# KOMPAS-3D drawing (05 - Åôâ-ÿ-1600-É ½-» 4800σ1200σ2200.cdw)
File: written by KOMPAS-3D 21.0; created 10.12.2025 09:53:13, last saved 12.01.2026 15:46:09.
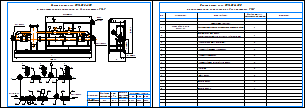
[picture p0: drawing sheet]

Sheets 1-2: A3, landscape

Document properties: Автор: RaskoAdmin; Форматы листов документа: 2xA3; Полное имя файла: \\ur38nt01\Departments\КТО\КБ ПУРДГ\Заявки\Прайс-лист на типовые шкафы ГРПШ\ПУГ-Ш-1600-Р л-п 4800х1200х2200.cdw

Title block, sheet 1: sheet number: 1; Количество листов документа: 2; Форматы листов документа: A3; stored path: \\ur38nt01\Departments\КТО\КБ ПУРДГ\Заявки\Прайс-лист на типовые шкафы ГРПШ\ПУГ-ШУЭО-65-Р л-п.cdw
Title block, sheet 2: sheet number: 2

Views: Вид 1
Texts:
  ЀdȀ
  Пункт учета газа ПУГ-Ш Ду200
  с измерительным комплексом на базе счетчика РГ-Р
  Вход Ду200
  Выход Ду200
  Н max
  Условный
  проход Ду, мм
  Qmax,
  Диапазон
  измерений
  Qmin/Qmax
  Габаритные размеры
  А, мм
  В, мм
  Н, мм
  ПУГ-Ш-1600-Р
  Поз.
  Условный проход
  расходомера Ду 200, мм
  СГ-ЭК-Р-(0,2...2,0)-
  Стандартные изделия
  Измерительный комплекс с ротационным счетчиком Ду200
  Фильтр газа ФГ Ду200
  (Оснащен индикатором перепада давления ДПД)
  Кран кнопочный под манометр
  Кран шаровой штуцерный Ду20
  Кран шаровый Ду150
  Кран шаровый с мехприводом Ду200
  Манометр
  Отвод Ду150
  Фланец Ду150
  Фланец Ду200
  Ду20
  Свеча
  POLYLINE_STYLE_0.18_RGB_0_0_0
  POLYLINE_STYLE_0.77_RGB_0_0_0
  PHANTOM_RGB_255_0_191_SC_1_THICK_0.15
  СONTINUOUS_RGB_0_0_0_THICK_0.25
  K5LT32768_RGB_0_0_0_THICK_0.25
  K5LT32769_RGB_128_128_128_THICK_0.25
  K5LT32770_RGB_0_0_0_THICK_0.7
  ACISOTGL_RGB_255_0_0_SC_1_THICK_0.2
  POLYLINE_STYLE_0.50_RGB_0_0_0
  ACISOTGL_RGB_0_0_0_SC_1_THICK_0.18
  ACISOTGL_RGB_0_0_0_SC_1_THICK_0.15
  Без основной надписи.
Dimensions and other numbers on the sheet: 1; 2; 4; 3; 5; 6; 7; 8; 9; 10; 800; 3000±1000; 200; 1600; 10/1600; 4800; 1200; 2200; -1600/1,6; 1:15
